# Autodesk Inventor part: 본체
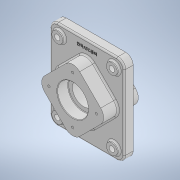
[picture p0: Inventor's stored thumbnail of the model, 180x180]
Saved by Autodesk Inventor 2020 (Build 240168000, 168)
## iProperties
Created: 2021-07
Part Number: 본체
Material: 일반
Document SubType Name: Modeling
Designer: Owner
Density: 1 g/cm^3
Appearance: 기본값
Mass: 808.059 g
Surface Area: 962.145 cm^2
Volume: 808.059 cm^3
Author: Owner
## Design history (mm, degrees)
sketch "스케치1"
  geometry: L1 (-75, -90)-(75, -90); L2 (75, -90)-(75, 90); L3 (75, 90)-(-75, 90); L4 (-75, 90)-(-75, -90); L5 (-75, -90)-(75, 90); L6 (75, -90)-(-75, 90); 1 further point
  constraints: 12 end point, 2 midpoint, 2 parallel, 1 horizontal, 1 perpendicular
  dimensions: "d0" = 150 distance of L3.end L2.end; "d1" = 180 distance of L2.end L1.end
extrude "돌출1" new body sketch "스케치1" stored distance "d2" = 18; taper "d3" = 0 deg
fillet "모깎기1" dims "d4" = 15
sketch "스케치2"
  geometry: L1 (0, -70.711)-(70.711, 0); L2 (70.711, 0)-(0, 70.711); L3 (0, 70.711)-(-70.711, 0); L4 (-70.711, 0)-(0, -70.711); L5 (0, -70.711)-(0, 70.711); L6 (70.711, 0)-(-70.711, 0); 2 further points
  constraints: 12 end point, 3 midpoint, 2 parallel, 1 perpendicular, 1 vertical alignment
  dimensions: "d5" = 100 distance of L1.end L2.end; "d6" = 100 distance of L1.start L1.end
extrude "돌출2" join sketch "스케치2" distance "d7" = 23; taper "d8" = 0 deg
sketch "스케치3"
  geometry: L1 (0, 70.711)-(-70.711, 0) reference; L2 (70.711, 0)-(0, 70.711) reference; L3 (0, -70.711)-(70.711, 0) reference; L4 (-70.711, 0)-(0, -70.711) reference; 1 further point
extrude "돌출3" join sketch "스케치3" distance "d9" = 29; taper "d10" = 0 deg
sketch "스케치4"
  geometry: C1 r 31 at (0, 0); 2 further points
  constraints: 2 coincident, 1 centre point
  dimensions: "d11" = 62 diameter of C1
extrude "돌출4" cut sketch "스케치4" distance "d12" = 22; taper "d13" = 0 deg
sketch "스케치5"
  geometry: C1 r 31 at (0, 0) reference; 1 further point
extrude "돌출5" cut sketch "스케치5" distance "d14" = 22; taper "d15" = 0 deg
fillet "모깎기2" dims "d16" = 20
sketch "스케치6"
  geometry: 2 further points
  constraints: 1 vertical alignment
  dimensions: "d17" = 48 distance of point (0, 0) point (0, 48)
hole "구멍1" sketch "스케치6" at (0, 48) diameter "d18" = 4.917; stored, may be unused: countersink angle "d22" = 90 deg, drill point angle "d24" = 118 deg; dims "d19" = 10, "d20" = 4, "d21" = 2, "d23" = 13
sketch "스케치7"
  geometry: 2 further points
  constraints: 1 vertical alignment
  dimensions: "d28" = 48 distance of point (0, 0) point (0, 48)
hole "구멍2" sketch "스케치7" at (0, 48) diameter "d29" = 4.917; stored, may be unused: countersink angle "d33" = 90 deg, drill point angle "d35" = 118 deg; dims "d30" = 10, "d31" = 4, "d32" = 2, "d34" = 13
sketch "스케치10"
  geometry: C1 r 31 at (0, 0) reference; C2 r 22.5 at (0, 0); 1 further point
  constraints: 1 centre point, 1 coincident
  dimensions: "d49" = 45 diameter of C2
extrude "돌출7" cut sketch "스케치10" extent not by distance; stored distance "d50" = 22; taper "d51" = 0 deg
sketch "스케치11"
  geometry: L1 (60, 90)-(-60, 90) reference; 2 further points
  constraints: 1 vertical alignment, 1 other
  dimensions: "d52" = 15 distance from line of L1 point (0, 75)
feature "엠보싱1" sketch "스케치11" dims "d0" = 150, "d1" = 180, "d53" = 0.5, "d54" = 0
chamfer "모따기1" distance "d55" = 1; stored, may be unused: second distance "d56" = 2, angle "d57" = 45 deg
fillet "모깎기3" dims "d58" = 1
fillet "모깎기5" dims "d60" = 3
fillet "모깎기6" dims "d61" = 3
fillet "모깎기7" dims "d62" = 3
sketch "스케치12"
  geometry: C1 r 11 at (-55, 70); 1 further point
  constraints: 1 centre point
  dimensions: "d63" = 22 diameter of C1; "d64" = 70 vertical distance of point (0, 0) C1.centre; "d65" = 55 horizontal distance of point (0, 0) C1.centre
extrude "돌출8" join sketch "스케치12" distance "d66" = 5; taper "d67" = 0 deg
sketch "스케치13"
  geometry: C1 r 11 at (0, 0) reference; 2 further points
  constraints: 1 coincident
hole "구멍4" sketch "스케치13" at (0, 0) diameter "d68" = 11; stored, may be unused: countersink angle "d72" = 90 deg, drill point angle "d74" = 118 deg; dims "d69" = 10, "d70" = 4, "d71" = 2, "d73" = 13
fillet "모깎기8" dims "d75" = 3
node "솔리드1"
pattern_circular "원형 패턴1" dims angle "d26" = 360 deg
pattern_circular "원형 패턴2" dims angle "d37" = 360 deg
mirror "미러4"
mirror "미러5"
feature "A9D066F2-1C7D-4E18-AEED-F7BC21143FA4" dims "d68" = 11, "d69" = 10, "d70" = 4, "d71" = 2, "d72" = 90 deg, "d73" = 13, "d74" = 118 deg
